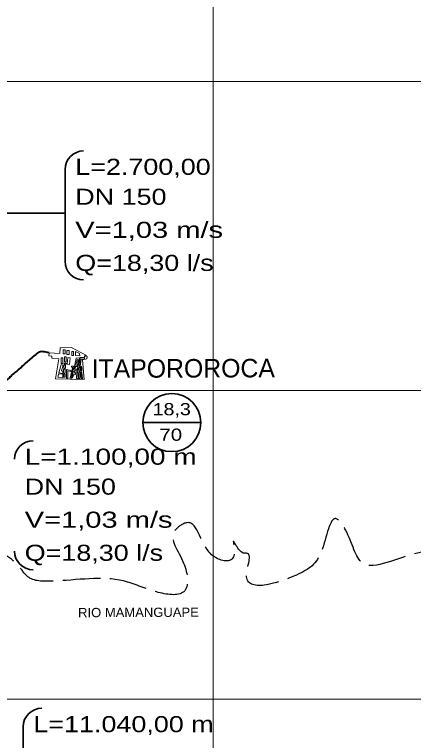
# Model space of a CAD drawing. Extents: x 0 to 1772, y 0 to 1188.
# Drawn here: x 892.9 to 975.1, y 181.7 to 331.4 of the extents above; entities that cross this region are included whole.
import ezdxf
from ezdxf.enums import TextEntityAlignment as Align

# ---------------------------------------------------------------- set-up
doc = ezdxf.new("R2010")
doc.units = 0
doc.header["$LTSCALE"] = 1.3
doc.linetypes.add('DOT_DASHED', pattern=[7.7, 5, -1.2, 0.3, -1.2])
doc.linetypes.add('LONG_DASHED', pattern=[7.5, 6, -1.5])
for name, color, linetype, lineweight in [('1', 7, 'DOT_DASHED', 13), ('5', 7, 'LONG_DASHED', 25), ('6', 7, 'Continuous', 40), ('63', 7, 'Continuous', 25), ('8', 7, 'Continuous', 35), ('9', 7, 'Continuous', 40)]:
    doc.layers.add(name, color=color, linetype=linetype, lineweight=lineweight)

msp = doc.modelspace()

# ---------------------------------------------------------------- linework, layer by layer
at = {"layer": '1', "linetype": 'Continuous'}
for points in [[(901.31, 256.257), (902.004, 260.405), (900.553, 260.5), (900.584, 260.971), (899.971, 261.011), (900.011, 261.624), (902.219, 261.48), (902.296, 262.659), (904.626, 262.709), (907.706, 261.067), (907.284, 261.004), (907.319, 260.775), (907.885, 260.86), (907.807, 260.36), (906.902, 260.159), (907.274, 256.101)], [(902.918, 261.45), (902.916, 262.269), (903.313, 262.27), (903.315, 261.451)], [(902.491, 259.401), (902.487, 260.605), (902.847, 260.606), (902.85, 259.402)], [(903.519, 259.764), (903.516, 260.806), (903.206, 260.805), (903.209, 259.763)], [(903.663, 261.266), (903.661, 262.085), (904.169, 262.087), (904.171, 261.268)], [(903.768, 259.268), (903.888, 260.658), (904.357, 260.618), (904.237, 259.227)], [(904.68, 261.108), (904.678, 261.927), (905.037, 261.928), (905.04, 261.109)], [(906.026, 258.803), (906.269, 260.603), (905.575, 260.527), (905.27, 258.838)], [(905.449, 261.098), (905.447, 261.917), (906.279, 261.472), (906.317, 261.038)], [(906.249, 258.779), (906.43, 260.654), (907.31, 260.693), (907.326, 260.35), (906.593, 260.317), (906.398, 258.854), (906.692, 258.814), (906.676, 258.693)], [(902, 257.5), (902.504, 259.19), (902.934, 259.061), (902.586, 257.894), (902.824, 257.823), (902.869, 257.391)], [(903.076, 258.447), (903.074, 259.104), (903.397, 259.105), (903.399, 258.448)], [(903.148, 259.291), (903.147, 259.514), (903.495, 259.515), (903.495, 259.292)], [(905.529, 259.062), (905.811, 260.267), (906.034, 260.215), (905.889, 259.014)], [(903.005, 257.453), (903.002, 258.248), (903.35, 258.249), (903.352, 257.454)], [(903.578, 256.412), (903.573, 258.163), (904.516, 258.004), (904.479, 257.787), (903.864, 257.89), (903.851, 256.426)], [(904.335, 256.415), (904.714, 257.955), (904.936, 257.9), (904.556, 256.36)], [(904.601, 258.675), (904.6, 258.886), (905.059, 258.887), (904.937, 258.117), (904.774, 258.143), (904.844, 258.59)], [(904.841, 257.148), (905.062, 257.881), (905.288, 257.813), (905.22, 257.587), (905.446, 257.519), (905.325, 257.116), (905.089, 257.187), (905.018, 256.952)], [(905.086, 258.08), (905.258, 258.739), (905.426, 258.695), (905.31, 258.248), (905.756, 258.132), (905.872, 258.578), (905.872, 258.578), (906.052, 258.418), (905.818, 257.896)], [(905.996, 256.333), (905.868, 257.772), (905.565, 257.745), (905.693, 256.306)], [(906.128, 257.86), (906.126, 258.605), (906.399, 258.605), (906.401, 257.861)], [(906.418, 256.309), (906.414, 257.657), (906.129, 257.656), (906.133, 256.308)], [(906.889, 256.286), (906.749, 257.626), (906.539, 257.604), (906.679, 256.264)], [(906.55, 257.836), (906.548, 258.581), (906.746, 258.582), (906.748, 257.837)], [(901.854, 256.817), (901.976, 257.276), (902.869, 257.205), (902.813, 256.505), (901.799, 256.586)], [(903.069, 256.585), (903.067, 257.218), (903.315, 257.218), (903.317, 256.585)], [(904.694, 256.378), (904.866, 256.95), (905, 256.91), (904.86, 256.446)]]:
    msp.add_lwpolyline(points, close=True, dxfattribs=at)
at = {"layer": '5'}
msp.add_spline([(987.842, 230.305), (985.628, 226.476), (982.964, 222.096), (976.206, 220.383), (964.658, 218.233), (961.115, 225.134), (959.277, 227.385), (956.197, 220.747), (950.998, 215.794), (940.713, 215.764), (940.699, 220.277), (940.263, 220.276), (938.015, 222.808), (938.024, 219.564), (934.079, 219.552), (928.422, 226.588), (925.891, 224.888), (927.742, 218.264), (927.76, 212.34), (922.124, 212.323), (915.354, 214.56), (900.56, 214.516), (895.639, 215.427), (893.532, 217.905), (890.518, 220.428), (888.219, 223.335), (886.162, 225.239), (883.344, 225.947), (879.87, 226.373)], degree=3, dxfattribs=at)
at = {"layer": '6'}
msp.add_spline([(900.011, 261.624), (898.769, 261.87), (898.141, 261.868), (897.279, 261.314), (896.18, 260.401), (895.236, 259.564), (894.548, 258.927), (893.539, 258.04), (892.746, 257.394), (891.965, 256.646), (891.359, 256.07), (890.879, 255.764), (890.301, 255.473), (889.863, 255.301), (889.199, 255.299), (887.983, 255.082), (887.246, 254.698), (886.65, 254.16), (885.617, 253.269), (884.707, 252.513), (884.098, 252.205), (883.587, 252.056), (883.052, 252.054), (882.455, 252.053), (881.771, 252.051), (881.003, 252.048), (880.111, 252.217), (879.304, 251.865), (878.186, 250.911)], degree=3, dxfattribs=at)
at = {"layer": '63', "lineweight": 13}
for p, q in [((933.807, 62.735), (933.807, 419.523)), ((1175.913, 317.583), (487.822, 317.583)), ((1175.913, 253.871), (487.822, 253.871)), ((1175.913, 190.159), (487.822, 190.159))]:
    msp.add_line(p, q, dxfattribs=at)
at = {"layer": '8'}
for p, q in [((903.308, 280.509), (903.308, 299.465)), ((894.671, 165.528), (894.671, 184.484))]:
    msp.add_line(p, q, dxfattribs=at)
msp.add_lwpolyline([(903.308, 290.466), (890.959, 290.466), (890.959, 255.994), (889.692, 259.561)], dxfattribs=at)
for centre, start, end in [((907.131, 299.465), 90, 180), ((907.131, 299.465), 90, 180), ((907.131, 299.465), 90, 180), ((907.131, 280.509), 180, 270), ((896.705, 239.662), 90, 180), ((896.705, 239.662), 90, 180), ((896.705, 239.662), 90, 180), ((896.705, 220.706), 180, 270), ((898.494, 184.484), 90, 180), ((898.494, 184.484), 90, 180), ((898.494, 184.484), 90, 180)]:
    msp.add_arc(centre, 3.823, start, end, dxfattribs=at)
at = {"layer": '9', "lineweight": 35}
msp.add_line((919.328, 247.235), (931.299, 247.235), dxfattribs=at)
msp.add_circle((925.314, 247.235), 5.985, dxfattribs=at)

# ---------------------------------------------------------------- texts
at = {"layer": '5', "width": 1.05}
msp.add_text('RIO MAMANGUAPE', height=1.911, rotation=0.211, dxfattribs=at).set_placement((905.988, 207.084))
at = {"layer": '8'}
for s, width, p in [('L=2.700,00 ', 1.25, (905.405, 298.352)), ('DN 150', 1.25, (905.405, 292.172)), ('V=1,03 m/s', 1.35, (905.405, 285.348)), ('Q=18,30 l/s', 1.25, (905.405, 278.525)), ('L=1.100,00 m', 1.3, (894.979, 238.549)), ('DN 150', 1.25, (894.979, 232.369)), ('V=1,03 m/s', 1.35, (894.979, 225.546)), ('Q=18,30 l/s', 1.25, (894.979, 218.722)), ('L=11.040,00 m', 1.25, (896.768, 183.371))]:
    msp.add_text(s, height=3.319, dxfattribs=dict(at, width=width)).set_placement(p)
at = {"layer": '9'}
msp.add_text('ITAPOROROCA', height=3.823, rotation=0.17, dxfattribs=at).set_placement((908.791, 256.468))
for s, width, p in [('18,3', 1.2, (925.299, 248.745)), ('70', 1.25, (925.102, 243.483))]:
    msp.add_text(s, height=2.52, rotation=0.17, dxfattribs=dict(at, width=width)).set_placement(p, align=Align.CENTER)

doc.saveas('drawing.dxf')
